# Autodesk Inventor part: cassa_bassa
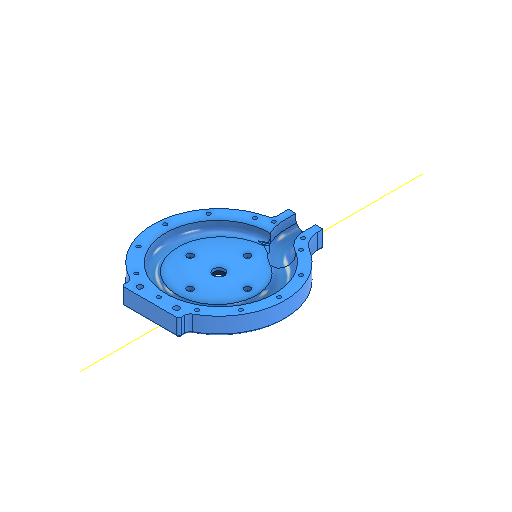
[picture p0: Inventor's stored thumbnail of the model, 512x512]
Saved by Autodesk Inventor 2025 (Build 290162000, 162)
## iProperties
Created: 2025-04
Part Number: cassa_bassa
Material: Generico
Document SubType Name: Modeling
Designer: R5800u
Density: 1 g/cm^3
Appearance: Ciano
d120: -110,000 mm
d123: -125,000 mm
Author: R5800u
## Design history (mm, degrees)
sketch "Schizzo1"
  geometry: C1 r 80 at (0, 0); 1 further point
  constraints: 1 centre point, 1 coincident
  dimensions: "d0" = 160 diameter of C1
sketch "Schizzo2"
  geometry: L1 (0, -80)-(0, 80) reference; L2 (9, -75.641)-(-9, -75.641); A1 r 10 centre (0, -80) between (-9, -75.641) and (9, -75.641); 1 further point
  constraints: 2 end point, 2 point on circle, 1 centre point, 1 coincident, 1 horizontal
  dimensions: "d1" = 20 diameter of A1; "d11" = 18 distance of L2.end L2.start
node "Piano di lavoro1"
sketch "Schizzo3"
  geometry: L1 (0, -80)-(0, 80) reference; L2 (9, 64.412)-(-9, 64.412); A1 r 18 centre (0, 80) between (9, 64.412) and (-9, 64.412); 1 further point
  constraints: 2 end point, 2 point on circle, 1 centre point, 1 coincident, 1 perpendicular
  dimensions: "d3" = 36 diameter of A1; "d10" = 18 distance of L2.end L2.start
loft "Loft1" sketch "Schizzo3" dims "d4" = 0, "d5" = 90 deg, "d6" = 0, "d7" = 90 deg, "d8" = 0, "d9" = 90 deg
sketch "Schizzo4"
  geometry: A1 r 18 centre (0, 0) between (15.588, 9) and (15.588, -9) reference; 1 further point
sketch "Schizzo5"
  geometry: L1 (-4.359, -9)-(-4.359, 9) reference; A1 r 10 centre (0, 0) between (-4.359, -9) and (-4.359, 9) reference; 1 further point
  node "Linea chiusa proiettata1"
loft "Loft2" dims "d12" = 0, "d13" = 90 deg, "d14" = 0, "d15" = 90 deg, "d16" = 0, "d17" = 90 deg
  node "Spigoli1"
  node "Spigoli2"
sketch "Schizzo6"
  geometry: L1 (-49, -84.87)-(-32.206, -55.782) reference; L2 (-10, -121.244)-(-10, -141.244); L3 (0, 0)-(0, -170.794); A1 r 60 centre (-70, -121.244) between (-10, -121.244) and (-40, -69.282); 1 further point
  constraints: 4 end point, 2 point on circle, 2 vertical, 1 centre point, 1 point on line, 1 tangent, 3 other
  dimensions: "d18" = 20 distance of L2.start L2.end; "d66" = 10 distance between parallel lines of L3 L2
node "Piano di lavoro2"
sketch "Schizzo7"
  geometry: C1 r 18 at (0, 0); 1 further point
  constraints: 1 centre point
  dimensions: "d19" = 36 diameter of C1
loft "Loft3" sketch "Schizzo7" dims "d20" = 0, "d21" = 90 deg, "d22" = 0, "d23" = 90 deg, "d24" = 0, "d25" = 90 deg
  node "Spigoli3"
sketch "Schizzo9"
  geometry: C1 r 85.5 at (0, 0); 1 further point
  constraints: 1 centre point, 1 coincident
  dimensions: "d54" = 171 diameter of C1
extrude "Estrusione2" new body sketch "Schizzo9" stored distance "d37" = 20; taper "d38" = 0 deg
sketch "Schizzo8"
  geometry: L1 (-40.298, -107.708)-(-40.298, -141.244); L2 (-40.298, -141.244)-(19.702, -141.244); L3 (19.702, -141.244)-(19.702, -113.3); L4 (5.682, -141.244)-(8, -141.244) reference; A1 r 115 centre (0, 0) between (-40.298, -107.708) and (19.702, -113.3); 2 further points
  constraints: 6 end point, 2 perpendicular, 2 point on circle, 1 centre point, 1 coincident, 1 point on line, 1 vertical
  dimensions: "d34" = 230 diameter of A1; "d39" = 60 distance between parallel lines of L3 L1
extrude "Estrusione1" new body sketch "Schizzo8" stored distance "d35" = 50; taper "d36" = 0 deg
feature "Combina1"
  node "Solido1"
feature "Combina3"
  node "Solido3"
sketch "Schizzo10"
  geometry: L1 (0, 48.504)-(15.101, 48.504); L2 (15.101, 48.504)-(68.74, 10.012); L3 (68.74, 10.012)-(0, 10.012); L4 (0, 10.012)-(0, 48.504); L5 (68.74, 10.012)-(0, 10.012); L6 (0, 10.012)-(0, 4.744); L7 (0, 4.744)-(68.74, 4.744); L8 (68.74, 4.744)-(68.74, 10.012); 2 further points
  constraints: 16 end point, 3 parallel, 2 horizontal, 2 perpendicular
revolve "Rivoluzione1" sketch "Schizzo10" stored, may be unused: angle "d40" = 360 deg
sketch "Schizzo11"
  geometry: L1 (0, 48.504)-(15.101, 48.504) reference; L2 (15.101, 48.504)-(68.74, 10.012) reference; L3 (68.74, 10.012)-(0, 10.012) reference; L4 (0, 10.012)-(0, 48.504) reference; L5 (93.61, 2.012)-(27.101, 49.739); L6 (17.675, 56.504)-(-8, 56.504); L7 (-8, 56.504)-(-8, 2.012); L8 (-8, 2.012)-(93.61, 2.012); L9 (115, 25)-(-115, 25) reference; L10 (15.101, 48.504)-(15.101, 68.504); L11 (15.101, 68.504)-(27.101, 68.504); L12 (27.101, 68.504)-(27.101, 49.739); 5 further points
  constraints: 14 end point, 2 perpendicular, 1 vertical, 2 other
  dimensions: "d41" = 8 distance between parallel lines of L2 L5; "d69" = 20 distance of L1.end L10.end; "d70" = 12 distance of L10.end L11.end
revolve "Rivoluzione2" sketch "Schizzo11" stored, may be unused: angle "d42" = 90 deg
fillet "Raccordo1" dims "d43" = 15
fillet "Raccordo2" dims "d44" = 50
sketch "Schizzo12"
  geometry: C1 r 5.15 at (0, 0); 1 further point
  constraints: 1 centre point, 1 coincident
  dimensions: "d47" = 10.3 diameter of C1
extrude "Estrusione3" cut sketch "Schizzo12" extent not by distance; stored distance "d48" = 0; taper "d49" = 0 deg
fillet "Raccordo5" dims "d50" = 20
fillet "Raccordo11" dims "d59" = 5
fillet "Raccordo8" dims "d56" = 40
fillet "Raccordo9" dims "d57" = 10
chamfer "Smusso1" distance "d63" = 1; stored, may be unused: second distance "d64" = 2, angle "d65" = 45 deg
fillet "Raccordo15" dims "d68" = 2
sketch "Schizzo15"
  geometry: C1 r 2.15 at (-25, 0) reference; 1 further point
extrude "Estrusione5" cut sketch "Schizzo15" distance "d81" = 25; taper "d82" = 0 deg
pattern_circular "Serie circolare2" dims angle "d84" = 360 deg
sketch "Schizzo16" dims "d86" = 210
  geometry: C1 r 5.15 at (0, 0) reference; 3 further points
  constraints: 1 coincident, 1 vertical alignment, 2 other
hole "Foro2" sketch "Schizzo16" at (0, -105) diameter "d87" = 6.4; stored, may be unused: countersink angle "d91" = 90 deg, drill point angle "d93" = 118 deg; dims "d88" = 6, "d89" = 11, "d90" = 10, "d92" = 30
sketch "Schizzo17"
  geometry: L1 (6.466, 105)-(3.233, 99.4); L2 (3.233, 99.4)-(-3.233, 99.4); L3 (-3.233, 99.4)-(-6.466, 105); L4 (-6.466, 105)-(-3.233, 110.6); L5 (-3.233, 110.6)-(3.233, 110.6); L6 (3.233, 110.6)-(6.466, 105); C1 r 1.229 at (0, 100) reference; C2 r 3.2 at (0, 105) reference; 2 further points
  constraints: 12 end point, 1 coincident, 13 other
  dimensions: "d94" = 11.2 distance between parallel lines of L2 L5
extrude "Estrusione6" cut sketch "Schizzo17" distance "d95" = 10; taper "d96" = 0 deg
pattern_circular "Serie circolare3" dims "d98" = 160 deg
pattern_circular "Serie circolare4" dims "d101" = 150 deg
sketch "Schizzo18"
  geometry: 3 further points
hole "Foro3" sketch "Schizzo18" at (36.774, 110.222), (-13.687, 109.855) diameter "d103" = 6.4; stored, may be unused: countersink angle "d107" = 90 deg, drill point angle "d109" = 118 deg; dims "d104" = 6, "d105" = 11, "d106" = 10, "d108" = 8
sketch "Schizzo19"
  geometry: L1 (-13.687, -116.783)-(-19.687, -113.319); L2 (-19.687, -113.319)-(-19.687, -106.391); L3 (-19.687, -106.391)-(-13.687, -102.927); L4 (-13.687, -102.927)-(-7.687, -106.391); L5 (-7.687, -106.391)-(-7.687, -113.319); L6 (-7.687, -113.319)-(-13.687, -116.783); L7 (36.774, -117.15)-(30.774, -113.686); L8 (30.774, -113.686)-(30.774, -106.758); L9 (30.774, -106.758)-(36.774, -103.293); L10 (36.774, -103.293)-(42.774, -106.758); L11 (42.774, -106.758)-(42.774, -113.686); L12 (42.774, -113.686)-(36.774, -117.15); C1 r 3.2 at (-13.687, -109.855) reference; C2 r 3.2 at (36.774, -110.222) reference; 3 further points
  constraints: 24 end point, 2 coincident, 26 other
  dimensions: "d110" = 12 distance between parallel lines of L5 L2; "d111" = 12 distance between parallel lines of L11 L8
extrude "Estrusione7" cut sketch "Schizzo19" distance "d112" = 10; taper "d113" = 0 deg
node "Piano di lavoro3"
sketch "Schizzo20"
  geometry: L1 (50, -25)-(-50, -25); L2 (-50, -25)-(-50, 25); L3 (-50, 25)-(50, 25); L4 (50, 25)-(50, -25); L5 (50, -25)-(-50, 25); L6 (-50, -25)-(50, 25); 1 further point
  constraints: 12 end point, 2 midpoint, 2 parallel, 1 horizontal, 1 perpendicular
  dimensions: "d115" = 100 distance of L2.end L3.end; "d116" = 50 distance of L1.end L2.end
extrude "Estrusione8" join sketch "Schizzo20" stored distance "d117" = 10; taper "d118" = 0 deg
fillet "Raccordo16" dims "d119" = 10
node "Piano di lavoro4"
sketch "Schizzo21"
  geometry: L1 (111.351, 191.723)-(-143.413, 191.723); L2 (-143.413, 191.723)-(-143.413, -244.583); L3 (-143.413, -244.583)-(111.351, -244.583); L4 (111.351, -244.583)-(111.351, 191.723); 1 further point
  constraints: 8 end point, 2 parallel, 1 horizontal, 1 perpendicular
extrude "Estrusione9" cut sketch "Schizzo21" extent not by distance; stored distance "d121" = 0; taper "d122" = 0 deg
node "Piano di lavoro5"
sketch "Schizzo22"
  geometry: L1 (131.776, 82.162)-(-128.363, 82.162); L2 (-128.363, 82.162)-(-128.363, -33.889); L3 (-128.363, -33.889)-(131.776, -33.889); L4 (131.776, -33.889)-(131.776, 82.162); 1 further point
  constraints: 8 end point, 2 parallel, 1 horizontal, 1 perpendicular
extrude "Estrusione10" cut sketch "Schizzo22" extent not by distance; stored distance "d124" = 0; taper "d125" = 0 deg
fillet "Raccordo17" dims "d126" = 3
sketch "Schizzo23"
  geometry: C1 r 15.101 at (0, 0) reference; C2 r 17.101 at (0, 0); C3 r 19.101 at (0, 0); 1 further point
  constraints: 2 centre point
  dimensions: "d127" = 2 radial gap between concentric circles of C1 C2; "d128" = 2 radial gap between concentric circles of C2 C3
extrude "Estrusione11" cut sketch "Schizzo23" distance "d129" = 1.5; taper "d130" = 0 deg
fillet "Raccordo18" dims "d131" = 1
sketch "Schizzo24"
  geometry: 2 further points
  dimensions: "d132" = 21 distance of point (0, 0) point (0, -21)
hole "Foro4" sketch "Schizzo24" at (0, -21) diameter "d133" = 5.3; stored, may be unused: countersink angle "d137" = 90 deg, drill point angle "d139" = 118 deg; dims "d134" = 6, "d135" = 5.5, "d136" = 2.6, "d138" = 10
pattern_circular "Serie circolare5" dims angle "d141" = 360 deg
sketch "Schizzo25"
  geometry: L1 (27.298, -25)-(3.298, -25); L2 (27.298, -25)-(27.298, -22.761); L3 (27.298, -22.761)-(27.298, -1); A1 r 24 centre (27.298, -25) between (3.298, -25) and (27.298, -1); 10 further points
  constraints: 6 end point, 5 symmetric about line, 2 coincident, 2 point on circle, 2 point on line, 1 centre point, 1 horizontal
  dimensions: "d143" = 48 diameter of A1; "d154" = 19 distance of L1.end point (9.269, -6.963); "d164" = 24 distance of L1.start point (27.298, -1)
hole "Foro5" sketch "Schizzo25" at (3.298, -25), (9.269, -6.963), (9.269, -43.037), (45.327, -43.037), (45.327, -6.963), (51.298, -25) diameter "d144" = 5.3; stored, may be unused: countersink angle "d148" = 90 deg, drill point angle "d150" = 118 deg; dims "d145" = 6, "d146" = 4, "d147" = 2, "d149" = 10
node "Asse di lavoro1"
node "Piano di lavoro6"
sketch "Schizzo27"
  geometry: L1 (-27.5, 27.5)-(27.5, 27.5); L2 (27.5, 27.5)-(27.5, -27.5); L3 (27.5, -27.5)-(-27.5, -27.5); L4 (-27.5, -27.5)-(-27.5, 27.5); L5 (-27.5, 27.5)-(27.5, -27.5); L6 (27.5, 27.5)-(-27.5, -27.5); C1 r 5.15 at (0, 0) reference; C2 r 27.101 at (0, 0) reference; 1 further point
  constraints: 12 end point, 2 midpoint, 2 parallel, 1 horizontal, 1 perpendicular
  dimensions: "d158" = 55 distance of L2.end L3.end; "d159" = 55 distance of L1.end L2.end
extrude "Estrusione13" join sketch "Schizzo27" stored distance "d160" = 10; taper "d161" = 0 deg
fillet "Raccordo19" dims "d162" = 5
fillet "Raccordo20" dims "d163" = 4
node "Modifica diretta1"
node "Piano di lavoro7"
sketch "Schizzo28"
  geometry: L1 (97.318, -11.961)-(-53.167, -11.961); L2 (-53.167, -11.961)-(-53.167, 148.805); L3 (-53.167, 148.805)-(97.318, 148.805); L4 (97.318, 148.805)-(97.318, -11.961); 1 further point
  constraints: 8 end point, 2 parallel, 1 horizontal, 1 perpendicular
extrude "Estrusione14" cut sketch "Schizzo28" extent not by distance; stored distance "d169" = 0; taper "d170" = 0 deg
sketch "Schizzo29"
  geometry: C1 r 1.6 at (23.5, -33.5) reference; C2 r 1.6 at (-1.5, -58.5) reference; C3 r 1.6 at (23.5, -83.5) reference; C4 r 1.6 at (48.5, -58.5) reference; 1 further point
  node "Riferimento3"
  node "Riferimento4"
  node "Riferimento5"
  node "Riferimento6"
sketch "Schizzo30"
  geometry: 5 further points
hole "Foro6" sketch "Schizzo30" at (-23.73, -1.419), (1.27, 23.581), (1.27, -26.419), (26.27, -1.419) diameter "d173" = 3.2; stored, may be unused: countersink angle "d177" = 90 deg, drill point angle "d179" = 118 deg; dims "d174" = 6, "d175" = 5.5, "d176" = 3.5, "d178" = 8
fillet "Raccordo21" dims "d180" = 2
fillet "Raccordo22" dims "d181" = 6
sketch "Schizzo31"
  geometry: L1 (15.149, 129.122)-(42.149, 129.122) reference; L2 (16.602, 129.122)-(16.602, 110.545); L3 (40.71, 129.122)-(41.887, 113.611); C1 r 2.575 at (23.5, 58.5) reference; C2 r 1.6 at (49.75, 103.966) reference; C3 r 1.6 at (41.887, 113.611) reference; A1 r 52.5 centre (23.5, 58.5) between (16.602, 110.545) and (49.541, 104.086); A2 r 16.986 centre (58.53, 118.5) between (41.678, 116.368) and (49.541, 104.086); 5 further points
  constraints: 4 end point, 4 point on circle, 3 point on line, 2 centre point, 1 coincident, 1 perpendicular
  dimensions: "d182" = 105 diameter of A1
extrude "Estrusione16" cut sketch "Schizzo31" distance "d183" = 0.6; taper "d184" = 0 deg
fillet "Raccordo23" dims "d185" = 2
sketch "Schizzo32"
  geometry: C1 r 2.575 at (8.351, 70.622) reference; C2 r 8 at (8.351, 70.622); 1 further point
  constraints: 1 centre point, 1 coincident
  dimensions: "d186" = 16 diameter of C2
extrude "Estrusione17" cut sketch "Schizzo32" distance "d187" = 5.2; taper "d188" = 0 deg
sketch "Schizzo33"
  geometry: C1 r 2.575 at (0, 0) reference; C2 r 5 at (0, 0); 1 further point
  constraints: 1 centre point, 1 coincident
  dimensions: "d189" = 10 diameter of C2
extrude "Estrusione18" cut sketch "Schizzo33" distance "d190" = 5; taper "d191" = 0 deg
sketch "Schizzo34"
  geometry: L1 (8.351, 70.622)-(8.351, 137.843); L2 (31.351, 130.622)-(-14.649, 130.622) reference; C1 r 5 at (8.351, 70.622) reference; 3 further points
  constraints: 2 end point, 1 symmetric about line, 1 vertical
  dimensions: "d192" = 16 distance from line of L1 point (24.351, 123.622); "d193" = 7 distance from line of L2 point (24.351, 123.622)
hole "Foro7" sketch "Schizzo34" at (24.351, 123.622), (-7.649, 123.622) diameter "d194" = 5; stored, may be unused: countersink angle "d198" = 90 deg, drill point angle "d200" = 118 deg; dims "d195" = 6, "d196" = 11, "d197" = 8, "d199" = 8
node "Solido2"
node "Riferimento1"
node "Riferimento2"
feature "Scala1"
other parameters: "d2" = 150 deg, "d155" = -15, "d165" = 5
